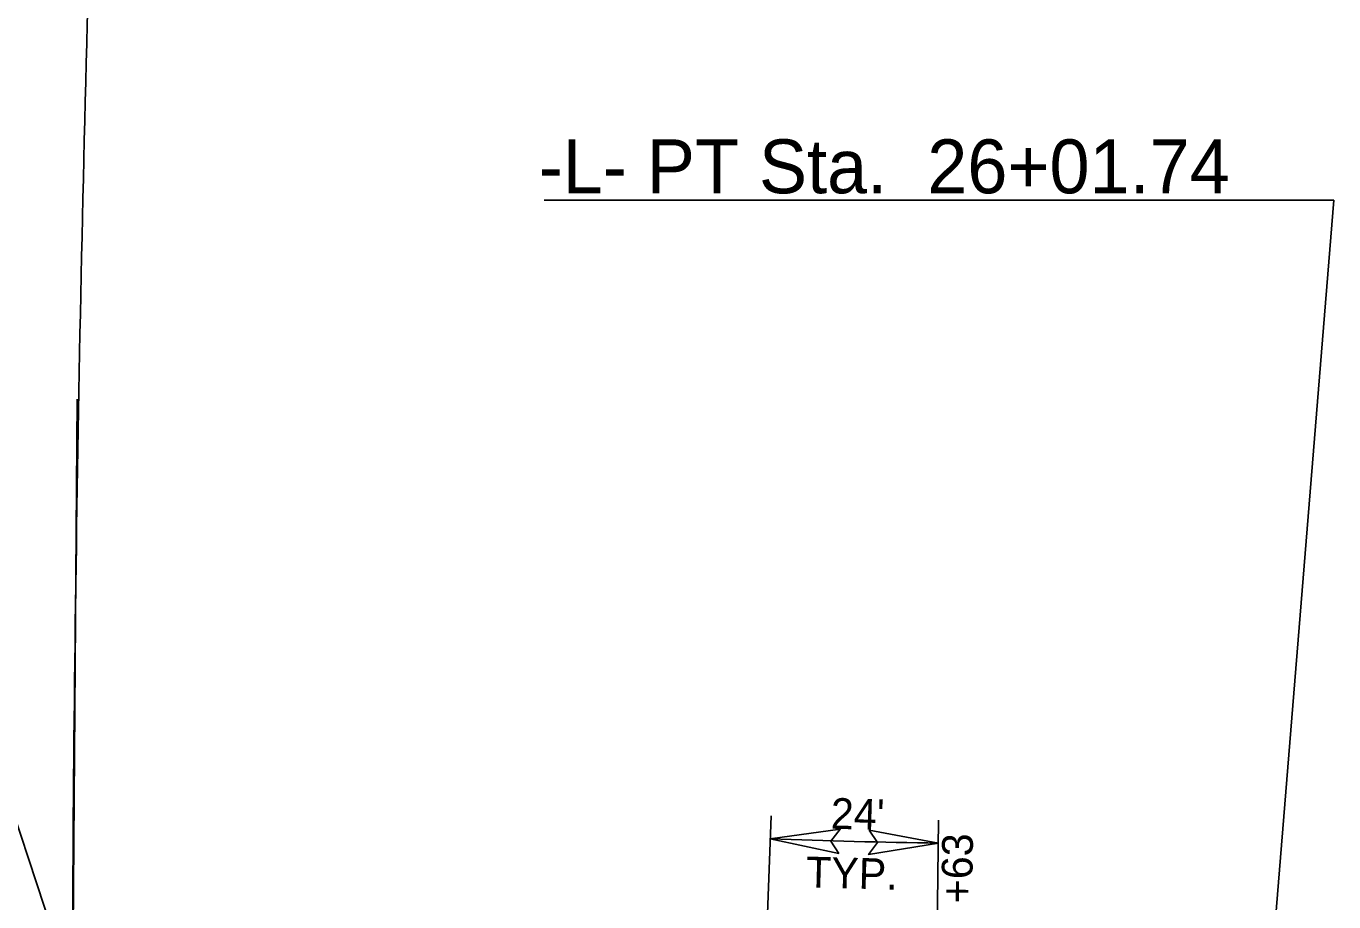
# Model space of a CAD drawing. Extents: x 1755545 to 1761252, y 736169 to 737766.
# Drawn here: x 1757129.5 to 1757299.3, y 737048.3 to 737162 of the extents above; entities that cross this region are included whole.
import ezdxf

# ---------------------------------------------------------------- set-up
doc = ezdxf.new("R2010")
doc.units = 0
for name, color, linetype in [('Exist Horizontal Alignment Station Label', 7, 'Continuous'), ('Prop Horizontal Alignment', 7, 'Continuous'), ('Prop Horizontal Alignment Station Label', 7, 'Continuous'), ('Prop Superelevation Label', 7, 'Continuous'), ('Prop Terminator CELL', 7, 'Continuous'), ('Raster_Level_0', 7, 'Continuous')]:
    doc.layers.add(name, color=color, linetype=linetype)

msp = doc.modelspace()

# ---------------------------------------------------------------- linework, layer by layer
at = {"layer": 'Exist Horizontal Alignment Station Label'}
msp.add_line((1757135.47, 737036.72), (1757085.26, 737188.57), dxfattribs=at)
at = {"layer": 'Prop Horizontal Alignment'}
msp.add_line((1757135.24, 736995.21), (1757136.11, 737113.56), dxfattribs=at)
at = {"layer": 'Prop Horizontal Alignment Station Label'}
for p in [(1757196.76, 737139.41), (1757285.64, 736971.25)]:
    msp.add_line(p, (1757299.32, 737139.41), dxfattribs=at)
at = {"layer": 'Prop Superelevation Label'}
for p, q in [((1757226.22, 737059.48), (1757223.67, 736991.72)), ((1757247.99, 737058.93), (1757247.16, 736991.84))]:
    msp.add_line(p, q, dxfattribs=at)
msp.add_arc((1757258.67, 737920.87), 865, 267.8426, 269.29008, dxfattribs=at)
at = {"layer": 'Prop Terminator CELL'}
for points in [[(1757235.04, 737054.59), (1757226.11, 737056.48), (1757235.21, 737057.74), (1757234, 737056.18)], [(1757238.97, 737057.59), (1757247.95, 737055.93), (1757238.89, 737054.45), (1757240.06, 737056.03)]]:
    msp.add_lwpolyline(points, close=True, dxfattribs=at)
at = {"layer": 'Raster_Level_0'}
msp.add_arc((1762390.7, 737018.29), 5255.26, 178.04642, 179.79908, dxfattribs=at)

# ---------------------------------------------------------------- texts
at = {"layer": 'Prop Horizontal Alignment Station Label'}
msp.add_text('-L- PT Sta.  26+01.74', height=7, rotation=360, dxfattribs=at).set_placement((1757196.05, 737140.31))
at = {"layer": 'Prop Superelevation Label'}
for s, rotation, p in [("24'", 358.4932, (1757233.94, 737057.8)), ('+63', 89.2901, (1757252.34, 737048.1)), ('TYP.', 358.4932, (1757230.73, 737050.19))]:
    msp.add_text(s, height=4, rotation=rotation, dxfattribs=at).set_placement(p)

doc.saveas('drawing.dxf')
